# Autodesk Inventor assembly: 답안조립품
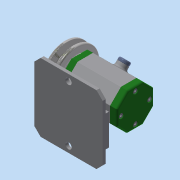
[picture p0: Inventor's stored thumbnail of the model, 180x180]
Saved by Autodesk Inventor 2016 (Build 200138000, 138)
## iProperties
Created: 2018-06
Part Number: 답안조립품
Material: 일반
Document SubType Name: Assembly
Designer: 602-10
Author: 602-10
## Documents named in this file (16)
- C:\Users\602-10\Desktop\480607V1001\답안조립품.iam
- C:\Users\602-10\Desktop\480607V1001\V벨트풀리.ipt
- C:\Users\602-10\Desktop\480607V1001\고무캡.ipt
- C:\Users\602-10\Desktop\480607V1001\너트 M8.ipt
- 너트 M8.ipt
- C:\Users\602-10\Desktop\480607V1001\뒤커버.ipt
- C:\Users\602-10\Desktop\480607V1001\베어링 15x32x9.ipt
- C:\Users\602-10\Desktop\480607V1001\본체.ipt
- C:\Users\602-10\Desktop\480607V1001\볼트 M4x12.ipt
- C:\Users\602-10\Desktop\480607V1001\스프링와셔 8.ipt
- C:\Users\602-10\Desktop\480607V1001\앞커버.ipt
- C:\Users\602-10\Desktop\480607V1001\오일 실 15 25 7.ipt
- C:\Users\602-10\Desktop\480607V1001\와셔 8x17.ipt
- C:\Users\602-10\Desktop\480607V1001\축.ipt
- C:\Users\602-10\Desktop\480607V1001\키 3x3x12.ipt
- 키 3x3x12.ipt
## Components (2 placed, 2 different names)
1. V벨트풀리:1 — 각도:1
2. 고무캡:1
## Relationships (1: Angle 1)
- 각도:1 [Angle]: V벨트풀리:1
